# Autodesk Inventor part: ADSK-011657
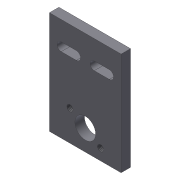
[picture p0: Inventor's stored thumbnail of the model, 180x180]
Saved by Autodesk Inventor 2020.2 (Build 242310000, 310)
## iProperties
Created: 2000-02
Part Number: ADSK-011657
Material: Pearson HRS
Document SubType Name: Modeling
Description: PLT-23,FH,BX,03,030,042,DROP DOWN TAB
Designer: sspink
Density: 7.83 g/cm^3
Appearance: Métal - Acier
Mass: 569.024 g
Surface Area: 205.087 cm^2
Volume: 72.6723 cm^3
Control State: 0
Checked Out: False
Master: False
Shininess: 0.0
Length Units: 11269
Angle Units: 11279
Time Units: 11290
Mass Units: 11283
Length Display Precision: 3
Angle Display Precision: 2
Compacted: True
Cutlength: 4.25
Material Desc: FLAT,HRS,0.375X03.000
Material_Number: A084408
Dimensions: 107x10x76 mm
Mass: 0,569 kg
VLT_Material: Pearson HRS
Density: 0.0
Volumn: 0.0
Area: 0.0
PropertySet Name: Model Information
Author: sspink
Revision Number: -
Title: PLT-23,FH,BX,03,030,042,DROP DOWN TAB
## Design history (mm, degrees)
node "Solide1"
  node "Extrusion1" dims "d2" = 10, "d3" = 0
  node "Extrusion2" dims "d10" = 9.525, "d11" = 0
  node "Hole1" dims "d13" = 22, "d14" = 9.525, "d15" = 6.35, "d16" = 60 deg, "d17" = 19.05, "d18" = 118 deg, "d30" = 6
  node "Hole2" dims "d23" = 6.647, "d24" = 9.525, "d25" = 6.35, "d26" = 60 deg, "d27" = 22.2, "d28" = 118 deg, "d33" = 16
sketch "Sketch1"
  geometry: L1 (-38, -53.5)-(38, -53.5); L2 (38, -53.5)-(38, 53.5); L3 (38, 53.5)-(-38, 53.5); L4 (-38, 53.5)-(-38, -53.5); 3 further points
  constraints: 8 end point, 2 midpoint, 2 parallel, 1 horizontal, 1 horizontal alignment, 1 perpendicular, 1 vertical alignment
  dimensions: "d0" = 76 distance between parallel lines of L2 L4; "d1" = 107 distance between parallel lines of L3 L1
sketch "Sketch2"
  geometry: L1 (-38, 53.5)-(38, 53.5) reference; L2 (-25.5, 33)-(-9.5, 33); L3 (-9.5, 33)-(-9.5, 24); L4 (-9.5, 24)-(-25.5, 24); L5 (-25.5, 24)-(-25.5, 33); L6 (9.5, 33)-(25.5, 33); L7 (25.5, 33)-(25.5, 24); L8 (25.5, 24)-(9.5, 24); L9 (9.5, 24)-(9.5, 33); L10 (-25.5, 28.5)-(-9.5, 28.5); L11 (9.5, 28.5)-(25.5, 28.5); L12 (-17.5, 28.5)-(17.5, 28.5); A1 r 4.5 centre (-25.5, 28.5) between (-25.5, 33) and (-25.5, 24); A2 r 4.5 centre (-9.5, 28.5) between (-9.5, 24) and (-9.5, 33); A3 r 4.5 centre (9.5, 28.5) between (9.5, 33) and (9.5, 24); A4 r 4.5 centre (25.5, 28.5) between (25.5, 24) and (25.5, 33); 2 further points
  constraints: 22 end point, 8 point on circle, 6 parallel, 4 centre point, 4 midpoint, 4 tangent, 3 perpendicular, 2 horizontal, 1 horizontal alignment, 1 vertical alignment
  dimensions: "d4" = 16 distance of L3.end L4.end; "d5" = 16 distance of L7.end L8.end (= d4); "d6" = 9 distance of L2.end L3.end; "d7" = 25 distance from line of L10.start L1; "d29" = 35 distance of L12.start L12.end
workaxis "Arbeitsachse1"
workplane "Arbeitsebene1"
sketch "Sketch3"
  geometry: L1 (38, -53.5)-(-38, -53.5) reference; L2 (-38, 53.5)-(38, 53.5) reference; L3 (0, 53.5)-(0, -53.5); 1 further point
  constraints: 2 end point, 2 midpoint, 1 point on line
  dimensions: "d12" = 22 distance from line of point (0, -31.5) L1
sketch "Sketch4"
  geometry: L1 (-16.25, -41.75)-(16.25, -21.25); C1 r 11 at (0, -31.5) reference; 1 further point
  constraints: 2 end point, 1 coincident, 1 midpoint
  dimensions: "d34" = 32.5 horizontal distance of L1.start L1.end; "d35" = 20.5 vertical distance of L1.start L1.end
node "Corps solides"
node "Corps surfaciques"
other parameters: "d36" = 90 deg
